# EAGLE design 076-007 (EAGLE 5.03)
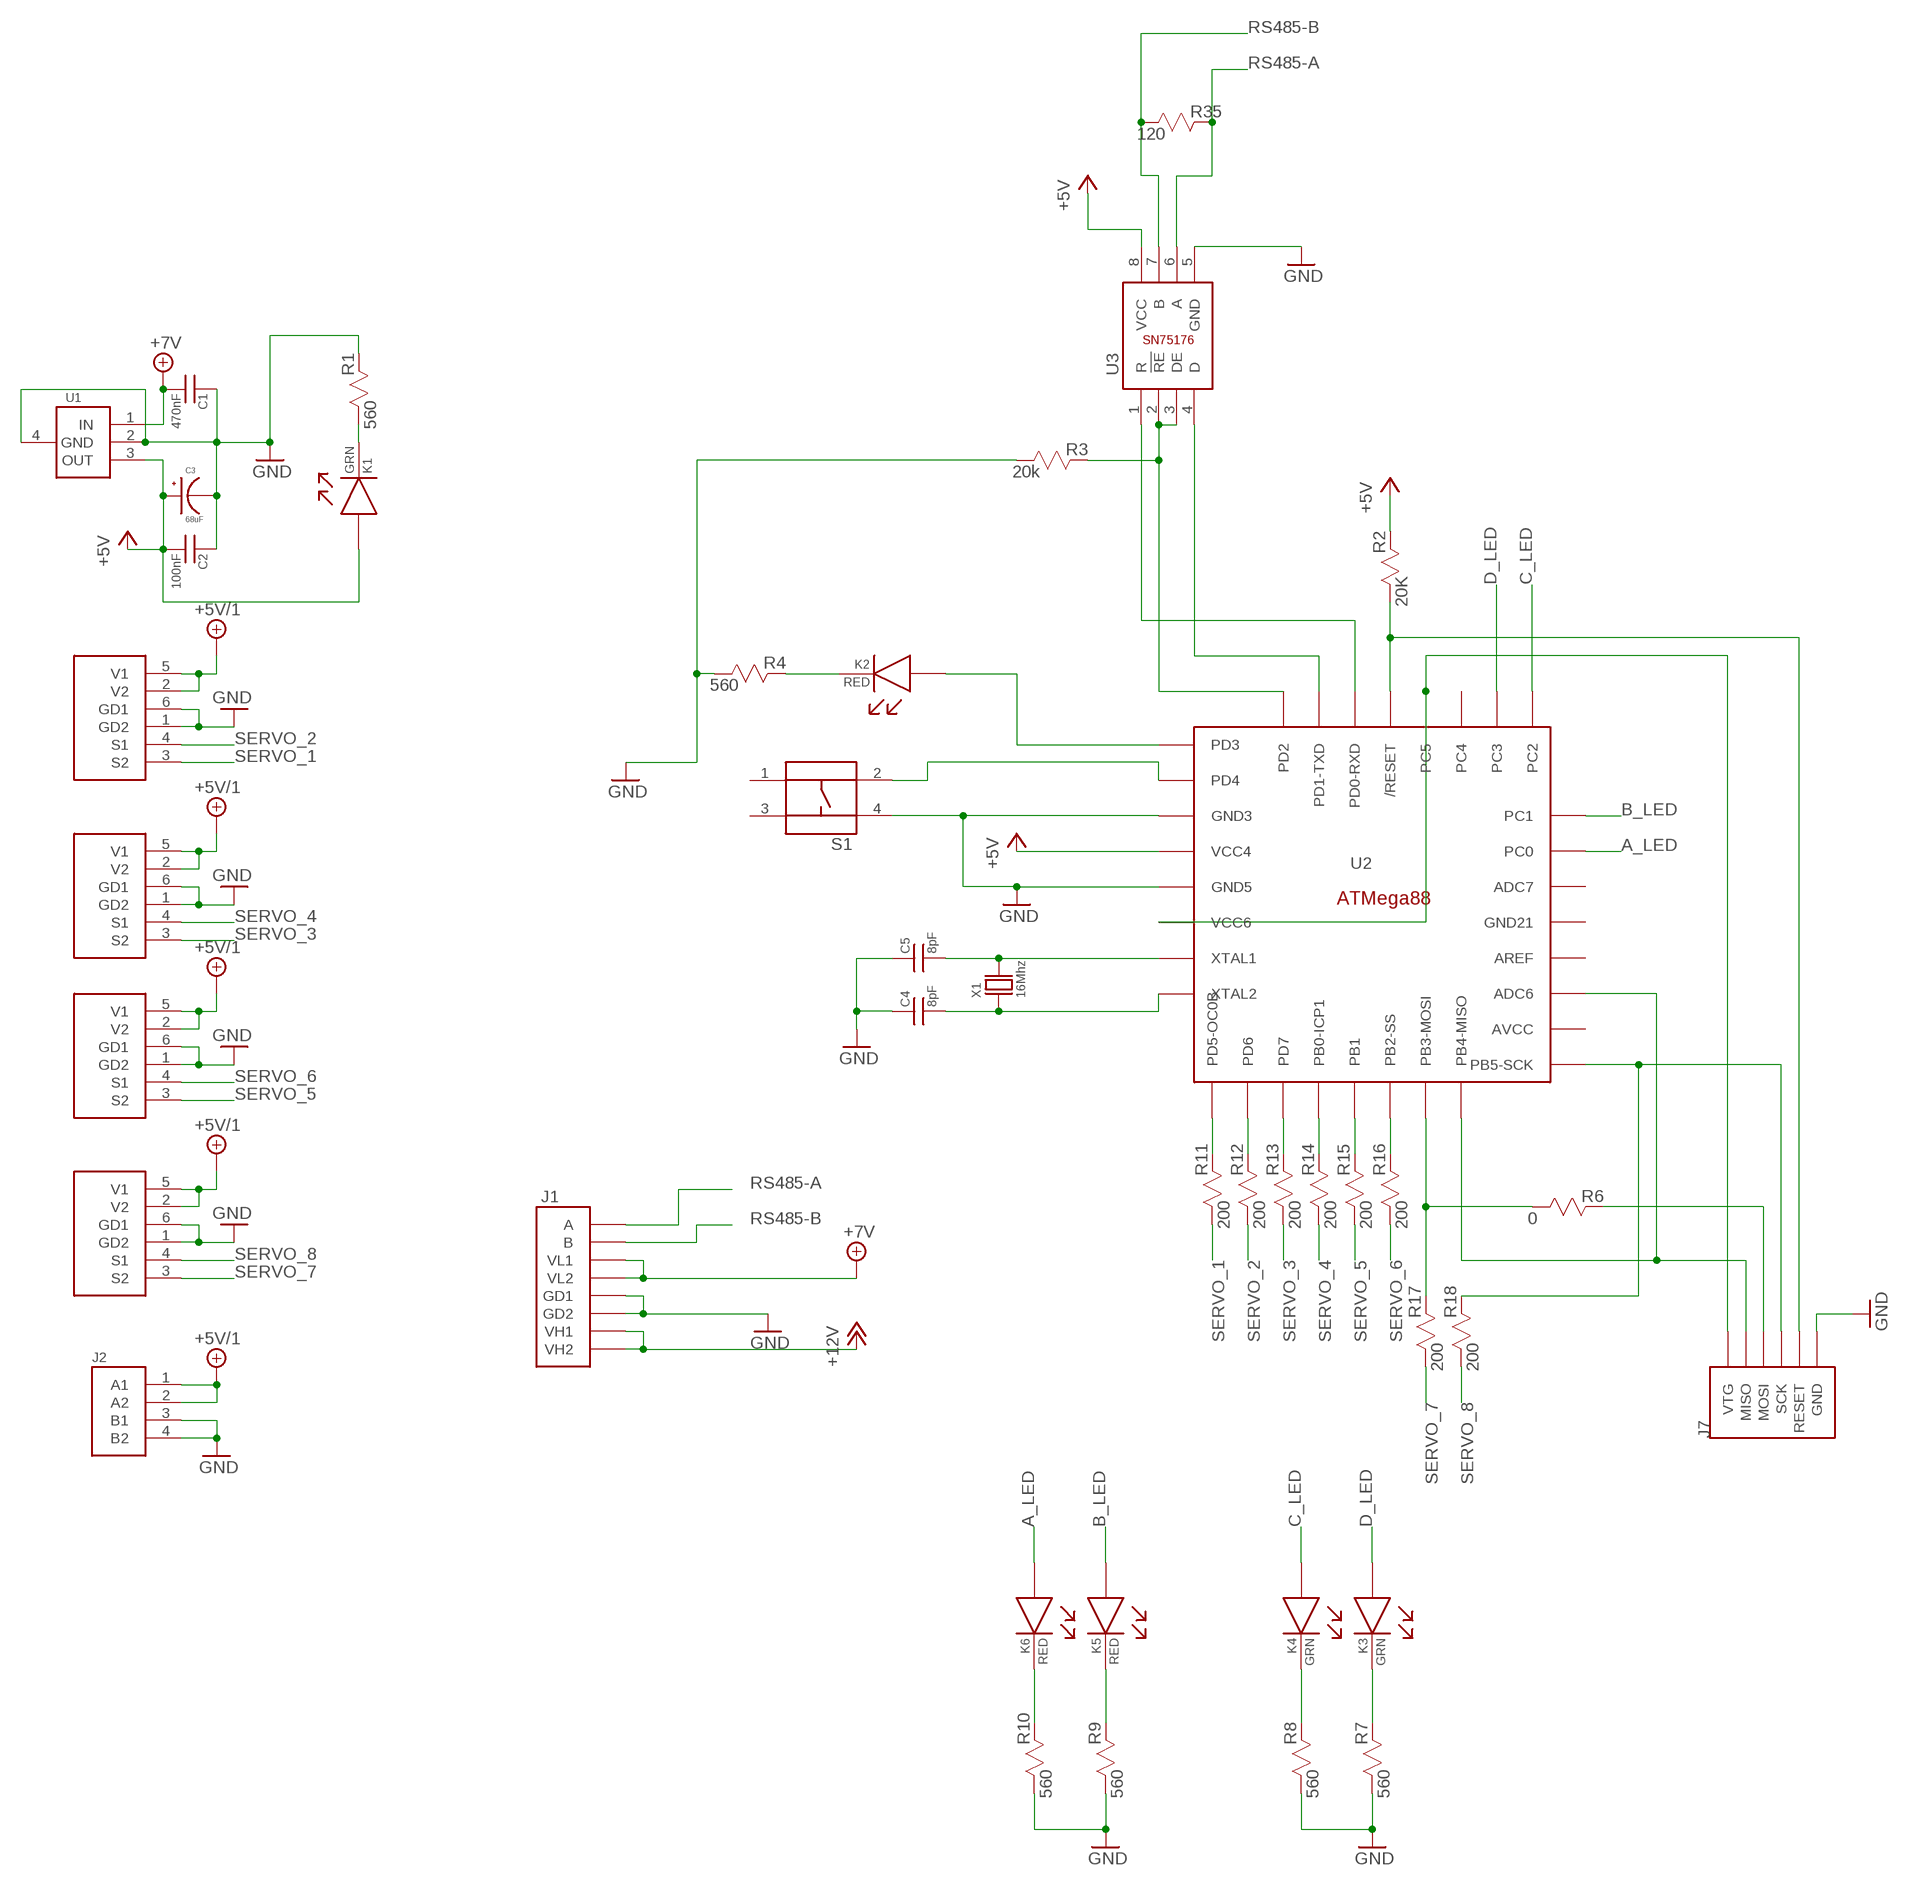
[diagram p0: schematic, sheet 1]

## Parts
C1  470nF  CAP_NONPOLARC1206  [C1206]
C2  100nF  CAP_NONPOLARC1206  [C1206]
C3  68uF  POLAR_CAPACITOR68UF  [ECAP-D8]
C4  8pF  CAP_NONPOLARC1206  [C1206]
C5  8pF  CAP_NONPOLARC1206  [C1206]
J1  IO_HEADER  [IO_HEADER]
J2  DC_MOTOR_HEADER  [2X2HEADER]
J3  SERVO_HEADER  [ISP_HEADER]
J4  SERVO_HEADER  [ISP_HEADER]
J5  SERVO_HEADER  [ISP_HEADER]
J6  SERVO_HEADER  [ISP_HEADER]
J7  ISP_HEADER  [ISP_HEADER]
K1  GRN  LED1206  [R1206]
K2  RED  LED1206  [R1206]
K3  GRN  LED1206  [R1206]
K4  GRN  LED1206  [R1206]
K5  RED  LED1206  [R1206]
K6  RED  LED1206  [R1206]
R1  560  RESISTORR1206  [R1206]
R2  20K  RESISTORR1206  [R1206]
R3  20k  RESISTORR1206  [R1206]
R4  560  RESISTORR1206  [R1206]
R6  0  RESISTORR1206  [R1206]
R7  560  RESISTORR1206  [R1206]
R8  560  RESISTORR1206  [R1206]
R9  560  RESISTORR1206  [R1206]
R10  560  RESISTORR1206  [R1206]
R11  200  RESISTORR1206  [R1206]
R12  200  RESISTORR1206  [R1206]
R13  200  RESISTORR1206  [R1206]
R14  200  RESISTORR1206  [R1206]
R15  200  RESISTORR1206  [R1206]
R16  200  RESISTORR1206  [R1206]
R17  200  RESISTORR1206  [R1206]
R18  200  RESISTORR1206  [R1206]
R35  120  RESISTORR1206  [R1206]
S1  PUSHBUTTON-SMD  [PUSHBUTTON-SMD]
U1  5VREG  [SOT223]
U2  ATMEGA88PA  [TQFP32-08]
U3  SN75176A  [SO08]
X1  16Mhz  XTAL-CSM7  [XTAL-CSM7]

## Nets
+5V: C2.2(M) C3.P K1.1(A) R2.2 U1.3(OUT) U2.4(VCC4) U3.8(VCC)
+5V/1: J2.1(A1) J2.2(A2) J3.2(V2) J3.5(V1) J4.2(V2) J4.5(V1) J5.2(V2) J5.5(V1) J6.2(V2) J6.5(V1)
+7V: C1.2(M) J1.3(VL1) J1.4(VL2) U1.1(IN)
+12V: J1.7(VH1) J1.8(VH2)
A_LED: K6.1(A) U2.23(PC0)
B_LED: K5.1(A) U2.24(PC1)
C_LED: K4.1(A) U2.25(PC2)
D_LED: K3.1(A) U2.26(PC3)
GND: C1.1(P) C2.1(P) C3.N C4.1(P) C5.1(P) J1.5(GD1) J1.6(GD2) J2.3(B1) J2.4(B2) J3.1(GD2) J3.6(GD1) J4.1(GD2) J4.6(GD1) J5.1(GD2) J5.6(GD1) J6.1(GD2) J6.6(GD1) J7.4(GND) R1.2 R3.1 R4.1 R7.1 R8.1 R9.1 R10.1 S1.4 U1.2(GND) U1.4(GND2) U2.3(GND3) U2.5(GND5) U3.5(GND)
MISO_WIRE: J7.1(MISO) U2.16(PB4-MISO) U2.19(ADC6)
MOSI: R6.1 R17.2 U2.15(PB3-MOSI)
N$1: K1.2(C) R1.1
N$2: J7.3(RESET) R2.1 U2.29(/RESET)
N$3: R11.2 U2.9(PD5-OC0B)
N$4: K6.2(C) R10.2
N$5: J7.2(SCK) R18.2 U2.17(PB5-SCK)
N$6: K2.2(C) R4.2
N$7: C4.2(M) U2.8(XTAL2) X1.1
N$8: C5.2(M) U2.7(XTAL1) X1.2
N$9: R3.2 U2.32(PD2) U3.2(!RE) U3.3(DE)
N$10: U2.30(PD0-RXD) U3.1(R)
N$11: U2.31(PD1-TXD) U3.4(D)
N$12: J7.6(VTG) U2.6(VCC6) U2.28(PC5)
N$13: S1.2 U2.2(PD4)
N$14: K5.2(C) R9.2
N$15: J7.5(MOSI) R6.2
N$16: K2.1(A) U2.1(PD3)
N$17: R12.2 U2.10(PD6)
N$18: R13.2 U2.11(PD7)
N$19: K3.2(C) R7.2
N$20: K4.2(C) R8.2
N$21: R14.2 U2.12(PB0-ICP1)
N$22: R15.2 U2.13(PB1)
N$23: R16.2 U2.14(PB2-SS)
RS485-A: J1.1(A) R35.2 U3.6(A)
RS485-B: J1.2(B) R35.1 U3.7(B)
SERVO_1: J3.3(S2) R11.1
SERVO_2: J3.4(S1) R12.1
SERVO_3: J4.3(S2) R13.1
SERVO_4: J4.4(S1) R14.1
SERVO_5: J5.3(S2) R15.1
SERVO_6: J5.4(S1) R16.1
SERVO_7: J6.3(S2) R17.1
SERVO_8: J6.4(S1) R18.1
Unconnected: S1.1 S1.3 U2.18(AVCC) U2.20(AREF) U2.21(GND21) U2.22(ADC7) U2.27(PC4)

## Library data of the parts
C1 C2 C4 C5 = Routroller:CAP_NONPOLAR
C3 = MtMM:POLAR_CAPACITOR
J1 = MtMM:IO_HEADER
J2 = MtMM:DC_MOTOR_HEADER
J3-J6 = MtMM:SERVO_HEADER
J7 = MtMM:ISP_HEADER
K1-K6 = MtMM:LED1206
R1-R4 R6-R18 R35 = Routroller:RESISTOR
S1 = MtMM:PUSHBUTTON-SMD
U1 = MtMM:5VREG
U2 = MtMM:ATMEGA88PA
U3 = Routroller:SN75176A
X1 = MtMM:XTAL-CSM7

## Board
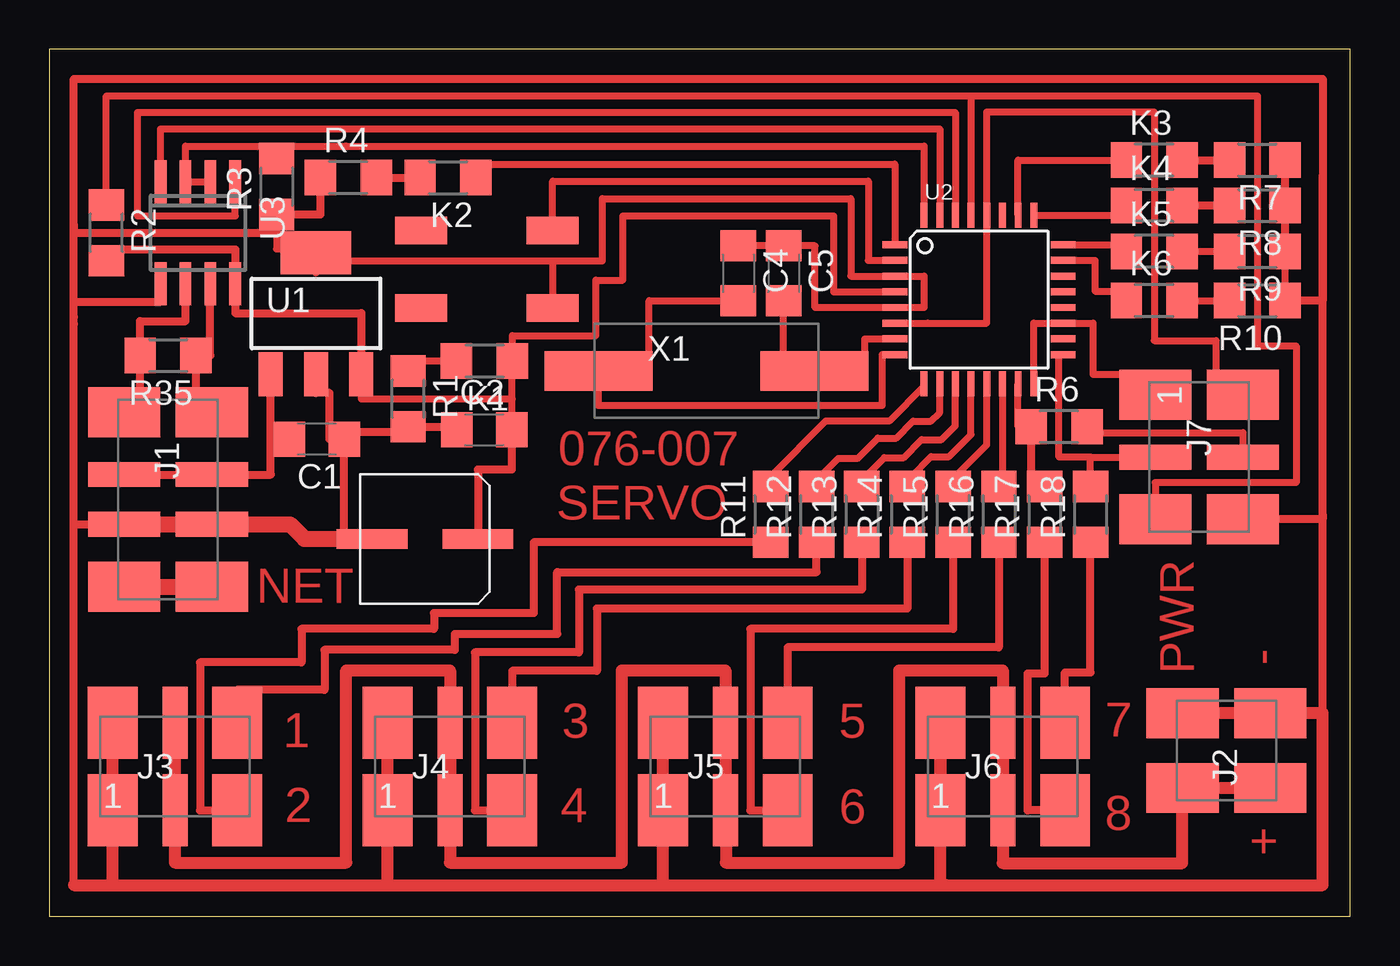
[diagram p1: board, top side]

Size 66.37 x 44.22 mm. Coordinates in mm from the lower left corner, seen from the top.
Outline: 0,0 66.37,0 66.37,44.22 0,44.22 0,0
Copper layers (1*16): Top 0.035mm / dielectric 1.5mm / Bottom 0.035mm
Design rules "default": minimum track width 10mil, minimum drill 24mil, track to track 8mil, track to pad 8mil, pad to pad 8mil, via to via 8mil, smd to smd 8mil, copper to edge 40mil, drill to drill 8mil, minimum pad ring 10mil, minimum via ring 8mil, stop-mask expansion 4mil, vias tented up to drill 0mil, thermal gap 10mil

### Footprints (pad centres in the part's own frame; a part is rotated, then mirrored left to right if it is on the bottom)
C1206 = smd 1.6 x 1.8: 1 -1.4,0; 2 1.4,0
ECAP-D8 = smd 3.6 x 1: N -2.7,0; P 2.7,0
IO_HEADER = smd 2.54 x 3.683: 1 -3.175,-2.235; 2 -3.175,2.235; 7 5.715,-2.235; 8 5.715,2.235 | smd 1.27 x 3.683: 3 0,-2.235; 4 0,2.235; 5 2.54,-2.235; 6 2.54,2.235
2X2HEADER = smd 2.54 x 3.683: 1 -1.905,-2.235; 2 -1.905,2.235; 3 1.905,-2.235; 4 1.905,2.235
ISP_HEADER = smd 2.54 x 3.683: 1 -3.175,-2.235; 3 3.175,-2.235; 4 3.175,2.235; 6 -3.175,2.235 | smd 1.27 x 3.683: 2 0,-2.235; 5 0,2.235
R1206 = smd 1.6 x 1.803: 1 -1.422,0; 2 1.422,0
PUSHBUTTON-SMD = smd 2.667 x 1.397: 1 3.353,-1.981; 2 -3.353,-1.981; 3 3.353,1.981; 4 -3.353,1.981
SOT223 = smd 1.219 x 2.235: 1 -2.311,-3.099; 2 0,-3.099; 3 2.311,-3.099 | smd 3.6 x 2.2: 4 0,3.099
TQFP32-08 = smd 1.27 x 0.356: 1 -4.293,2.8; 2 -4.293,2; 3 -4.293,1.2; 4 -4.293,0.4; 5 -4.293,-0.4; 6 -4.293,-1.2; 7 -4.293,-2; 8 -4.293,-2.8; 17 4.293,-2.8; 18 4.293,-2; 19 4.293,-1.2; 20 4.293,-0.4; 21 4.293,0.4; 22 4.293,1.2; 23 4.293,2; 24 4.293,2.8 | smd 0.356 x 1.27: 9 -2.8,-4.293; 10 -2,-4.293; 11 -1.2,-4.293; 12 -0.4,-4.293; 13 0.4,-4.293; 14 1.2,-4.293; 15 2,-4.293; 16 2.8,-4.293; 25 2.8,4.293; 26 2,4.293; 27 1.2,4.293; 28 0.4,4.293; 29 -0.4,4.293; 30 -1.2,4.293; 31 -2,4.293; 32 -2.8,4.293
SO08 = smd 0.6 x 2.2: 1 -1.905,-2.6; 2 -0.635,-2.6; 3 0.635,-2.6; 4 1.905,-2.6; 5 1.905,2.6; 6 0.635,2.6; 7 -0.635,2.6; 8 -1.905,2.6
XTAL-CSM7 = smd 5.5 x 2: 1 -5.5,0; 2 5.5,0

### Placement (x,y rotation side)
C1  13.67,24.33 180 top
C2  22.2,24.82 0 top
C3  19.18,19.25 0 top
C4  35.15,32.79 270 top
C5  37.47,32.79 270 top
J1  6.07,22.53 270 top
J2  60.05,8.46 90 top
J3  6.43,7.65 0 top
J4  20.45,7.65 0 top
J5  34.49,7.65 0 top
J6  48.64,7.65 0 top
J7  58.65,23.42 270 top
K1  22.2,28.32 180 top
K2  20.35,37.67 180 top
K3  56.36,38.56 0 top
K4  56.36,36.25 0 top
K5  56.36,33.91 0 top
K6  56.36,31.39 0 top
R1  18.31,26.39 270 top
R2  2.92,34.85 270 top
R3  11.61,37.21 90 top
R4  15.27,37.67 0 top
R6  51.51,24.97 0 top
R7  61.62,38.56 180 top
R8  61.62,36.25 180 top
R9  61.62,33.91 180 top
R10  61.62,31.39 180 top
R11  36.8,20.5 90 top
R12  39.14,20.5 90 top
R13  41.45,20.5 90 top
R14  43.76,20.5 90 top
R15  46.1,20.5 90 top
R16  48.44,20.5 90 top
R17  50.77,20.5 90 top
R18  53.11,20.5 90 top
R35  6.07,28.6 180 top
S1  22.33,32.99 180 top
U1  13.61,30.73 0 top
U2  47.42,31.45 0 top
U3  7.59,34.85 180 top
X1  33.53,27.81 0 top

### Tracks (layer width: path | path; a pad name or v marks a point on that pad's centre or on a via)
+5V
  Top 0.356: U2.4 40.01,31.84 40.01,35.71 29.26,35.71 29.26,32.44 27.89,32.44 27.89,29.62 23.62,29.62 K1.1 | K1.1 23.62,28.91 | 23.62,28.91 | U1.3 15.93,26.39 23.6,26.39 | K1.1 23.62,26.39 23.6,26.39 | K1.1 | 23.6,26.39 C2.2
  Top 0.406: R2.2 2.92,34.01 9.5,34.01 U3.8 9.5,30.76 15.93,30.76 U1.3 15.93,27.38 | C3.P 21.88,22.78 23.6,22.78 C2.2
+5V/1
  Top 0.61: J3.5 J3.2 6.43,2.74 15.16,2.74 15.16,12.55 20.45,12.55 J4.5 J4.2 20.45,2.74 29.21,2.74 29.21,12.55 34.49,12.55 J5.5 J5.2 34.52,2.74 43.36,2.74 43.36,12.55 48.64,12.55 J6.5 J6.2 48.64,2.72 57.78,2.72 57.78,6.55 J2.2 J2.1
+7V
  Top 0.356: 11.3,22.53 11.3,22.78
  Top 0.406: J1.3 J1.4 11.3,22.53 11.3,24.13 | 11.3,24.13 U1.1 | C1.2 12.82,24.13 11.3,24.13
+12V
  Top 0.406: J1.8 8,16.82
  Top 0.813: 2.41,16.82 J1.7 J1.8 8.48,16.82
A_LED
  Top 0.356: U2.23 53.34,33.45 53.34,31.88 54.94,31.88 K6.1
B_LED
  Top 0.356: U2.24 54.94,34.24 K5.1
C_LED
  Top 0.356: U2.25 54.94,35.74 K4.1
D_LED
  Top 0.356: U2.26 49.42,38.56 K3.1
GND
  Top 0.356: U1.4 13.61,32.82 | R10.1 R9.1 | 11.63,34.85 11.61,34.85 R3.1 11.61,34.04 13.61,34.04 | 25.68,33.43 14.94,33.43 arc-90 14.07,34.29 | 25.68,33.43 S1.4 | 25.68,33.43 28.22,33.43 28.22,36.6 40.89,36.6 40.89,32.65 U2.3 44.63,32.65 44.63,31.05 U2.5 39.06,31.05 39.06,34.19 C5.1 C4.1
  Top 0.406: 13.61,34.04 U1.4 14.07,34.29 | 64.95,1.6 64.95,20.5 | 64.95,20.5 64.95,37.74 | 64.95,37.74 64.95,42.7 1.27,42.7 1.27,35.26 | 1.27,1.6 1.27,19.99 | 1.27,30.2 1.27,31.34 | 1.27,31.34 1.27,35.26 | 64.95,37.74 64.95,37.59 | 1.27,30.2 1.27,30.56 | J7.4 64.95,20.24 64.95,20.5 | 1.27,19.99 J1.5 | 1.27,19.99 1.27,30.2 | 11.63,34.85 1.27,34.85 1.27,35.26 | U3.5 5.69,31.34 1.27,31.34 | R4.1 13.84,35.79 R3.1 | R7.1 R8.1 R9.1 | 64.95,37.74 64.95,31.39 R10.1 | U1.2 13.61,26.7 14.3,26.7 14.3,24.33 | 14.3,24.33 C1.1 15.06,24.71 18.31,24.71 R1.2 20.8,24.97 C2.1 | 14.94,19.25 15.04,19.25 15.04,24.33 14.3,24.33
  Top 0.61: 1.27,1.6 3.45,1.6 | 3.45,1.6 17.42,1.6 | 17.42,1.6 31.47,1.6 | 31.47,1.6 45.74,1.6 | 45.74,1.6 64.95,1.6 64.95,10.36 J2.3 J2.4 | J6.1 J6.6 45.47,1.6 45.74,1.6 | 31.47,1.6 31.32,1.6 J5.1 J5.6 | 17.42,1.6 17.27,1.6 J4.1 J4.6 | J3.6 J3.1 3.25,1.6 3.45,1.6
  Top 0.813: J1.5 J1.6 12.29,19.99 13.03,19.25 15.04,19.25 C3.N
MISO_WIRE
  Top 0.356: U2.16 50.22,29.46 50.22,30.25 U2.19 53.24,30.25 53.24,27.64 56.41,27.64 J7.1
MOSI
  Top 0.356: U2.15 49.42,24.97 R6.1
  Top 0.406: R17.2 50.09,21.92 R6.1
N$1
  Top 0.356: 18.31,28.32 K1.2
  Top 0.406: R1.1 18.31,28.32
N$2
  Top 0.356: 47.02,41.83 2.92,41.83 R2.1 | 47.02,41.83 U2.29 | 47.02,41.83 61.62,41.83 61.62,29.08 63.6,29.08 63.6,22.12 56.41,22.12 J7.3
N$3
  Top 0.356: U2.9 44.62,27.02 42.85,25.25 39.6,25.25 36.8,22.45 R11.2
N$4
  Top 0.356: K6.2 R10.2
N$5
  Top 0.356: 52.98,23.42 51.51,23.42 51.51,28.64 U2.17 | 52.98,23.42 J7.2 | R18.2 53.11,23.42 52.98,23.42
N$6
  Top 0.406: R4.2 K2.2
N$7
  Top 0.356: U2.8 42.49,28.64 42.49,26.06 28.02,26.06 28.02,27.81 X1.1 29.61,27.81 29.61,27.79 30.61,27.79 30.61,31.39 C4.2
N$8
  Top 0.356: U2.7 41.6,29.45 41.6,27.81 X1.2 37.59,27.81 | 37.59,27.81 37.44,27.81 | C5.2 37.47,27.81 37.59,27.81
N$9
  Top 0.356: U2.32 44.62,39.27 15.11,39.27 | 11.99,39.27 6.96,39.27 U3.3 U3.2 | 11.99,39.27 15.11,39.27 | 15.11,39.27 15.16,39.27 | R3.2 11.61,39.27 11.99,39.27
N$10
  Top 0.356: U2.30 46.22,41 4.52,41 4.52,35.71 9.5,35.71 U3.1
N$11
  Top 0.356: U2.31 45.42,40.16 5.69,40.16 U3.4
N$12
  Top 0.356: U2.6 44.8,30.25 arc90 44.81,30.25 47.82,30.25 U2.28 47.82,41.02 56.36,41.02 56.36,29.36 59.51,29.36 59.51,26.59 J7.6
N$13
  Top 0.356: U2.2 41.78,33.45 41.78,37.49 25.68,37.49 S1.2
N$14
  Top 0.356: K5.2 R9.2
N$15
  Top 0.356: J7.5 60.88,24.66 53.37,24.66 arc-90 R6.2
N$16
  Top 0.356: U2.1 43.13,38.35 22.3,38.35 22.3,37.67 K2.1
N$17
  Top 0.356: U2.10 45.42,25.69 44.98,25.25 44.07,25.25 43.2,24.38 42.27,24.38 41.22,23.34 40.23,23.34 39.4,22.5 39.4,22.17 R12.2
N$18
  Top 0.356: 42.16,21.92 R13.2 41.68,22.15 41.68,22.48 42.6,23.39 43.59,23.39 44.5,24.31 45.52,24.31 46.22,25.01 U2.11
N$19
  Top 0.406: K3.2 R7.2
N$20
  Top 0.406: K4.2 R8.2
N$21
  Top 0.356: R14.2 44.5,21.92 | R14.2 | U2.12 47.02,24.57 45.9,23.44 44.98,23.44 43.97,22.43 43.97,22.12 R14.2
N$22
  Top 0.356: 46.84,21.92 R15.2 46.38,22.2 46.38,22.61 47.82,24.05 U2.13
N$23
  Top 0.356: U2.14 48.62,22.1 R16.2
RS485-A
  Top 0.406: J1.1 4.65,26.52 R35.2 4.65,30.35 6.96,30.35 U3.6
RS485-B
  Top 0.406: 9.45,25.7 J1.2 7.49,26.52 R35.1 8.23,28.6 U3.7
SERVO_1
  Top 0.406: R11.1 24.71,19.08 24.71,15.47 19.63,15.47 19.63,14.66 12.88,14.66 12.88,12.95 7.7,12.95 7.7,5.41 J3.3
SERVO_2
  Top 0.356: 9.6,11.56 J3.4
  Top 0.406: R12.1 39.14,17.55 25.91,17.55 25.91,14.4 20.7,14.4 20.7,13.59 14.05,13.59 14.05,11.56 9.6,11.56
SERVO_3
  Top 0.406: R13.1 41.45,16.66 27.03,16.66 27.03,13.46 21.72,13.46 21.72,5.41 J4.3
SERVO_4
  Top 0.406: R14.1 43.76,15.7 27.94,15.7 27.94,12.52 23.62,12.52 J4.4
SERVO_5
  Top 0.406: R15.1 46.1,14.66 35.76,14.66 35.76,5.41 J5.3
SERVO_6
  Top 0.406: R16.1 48.44,13.72 37.67,13.72 J5.4
SERVO_7
  Top 0.406: J6.3 49.91,5.41 49.91,12.39 50.77,12.39 R17.1
SERVO_8
  Top 0.406: R18.1 53.11,12.45 51.82,12.45 J6.4

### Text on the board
Top: 076-007 | SERVO | NET | - | PWR | 1 | 3 | 5 | 7 | 2 | 4 | 6 | 8 | +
